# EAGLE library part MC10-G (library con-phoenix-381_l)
Mini-Combicon 3.81mm horizontal 10-polig (mit Gegenstecker)
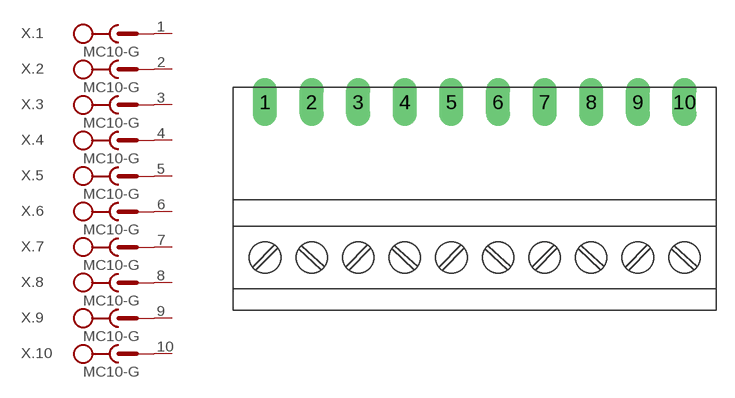
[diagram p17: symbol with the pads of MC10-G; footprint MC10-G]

Designator prefix X; gates .1=SK+V .2=SK+V .3=SK+V .4=SK+V .5=SK+V .6=SK+V .7=SK+V .8=SK+V .9=SK+V .10=SK+V

## MC10-G  [MC10-G]
1  .1:SK  pas
2  .2:SK  pas
3  .3:SK  pas
4  .4:SK  pas
5  .5:SK  pas
6  .6:SK  pas
7  .7:SK  pas
8  .8:SK  pas
9  .9:SK  pas
10  .10:SK  pas

## Footprint MC10-G (pad centres in mm)
Mini-Combicon 3.81mm horizontal 10-polig (mit Gegenstecker)
drill 1.3 long: 1 -17.145,0; 2 -13.335,0; 3 -9.525,0; 4 -5.715,0; 5 -1.905,0; 6 1.905,0; 7 5.715,0; 8 9.525,0; 9 13.335,0; 10 17.145,0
